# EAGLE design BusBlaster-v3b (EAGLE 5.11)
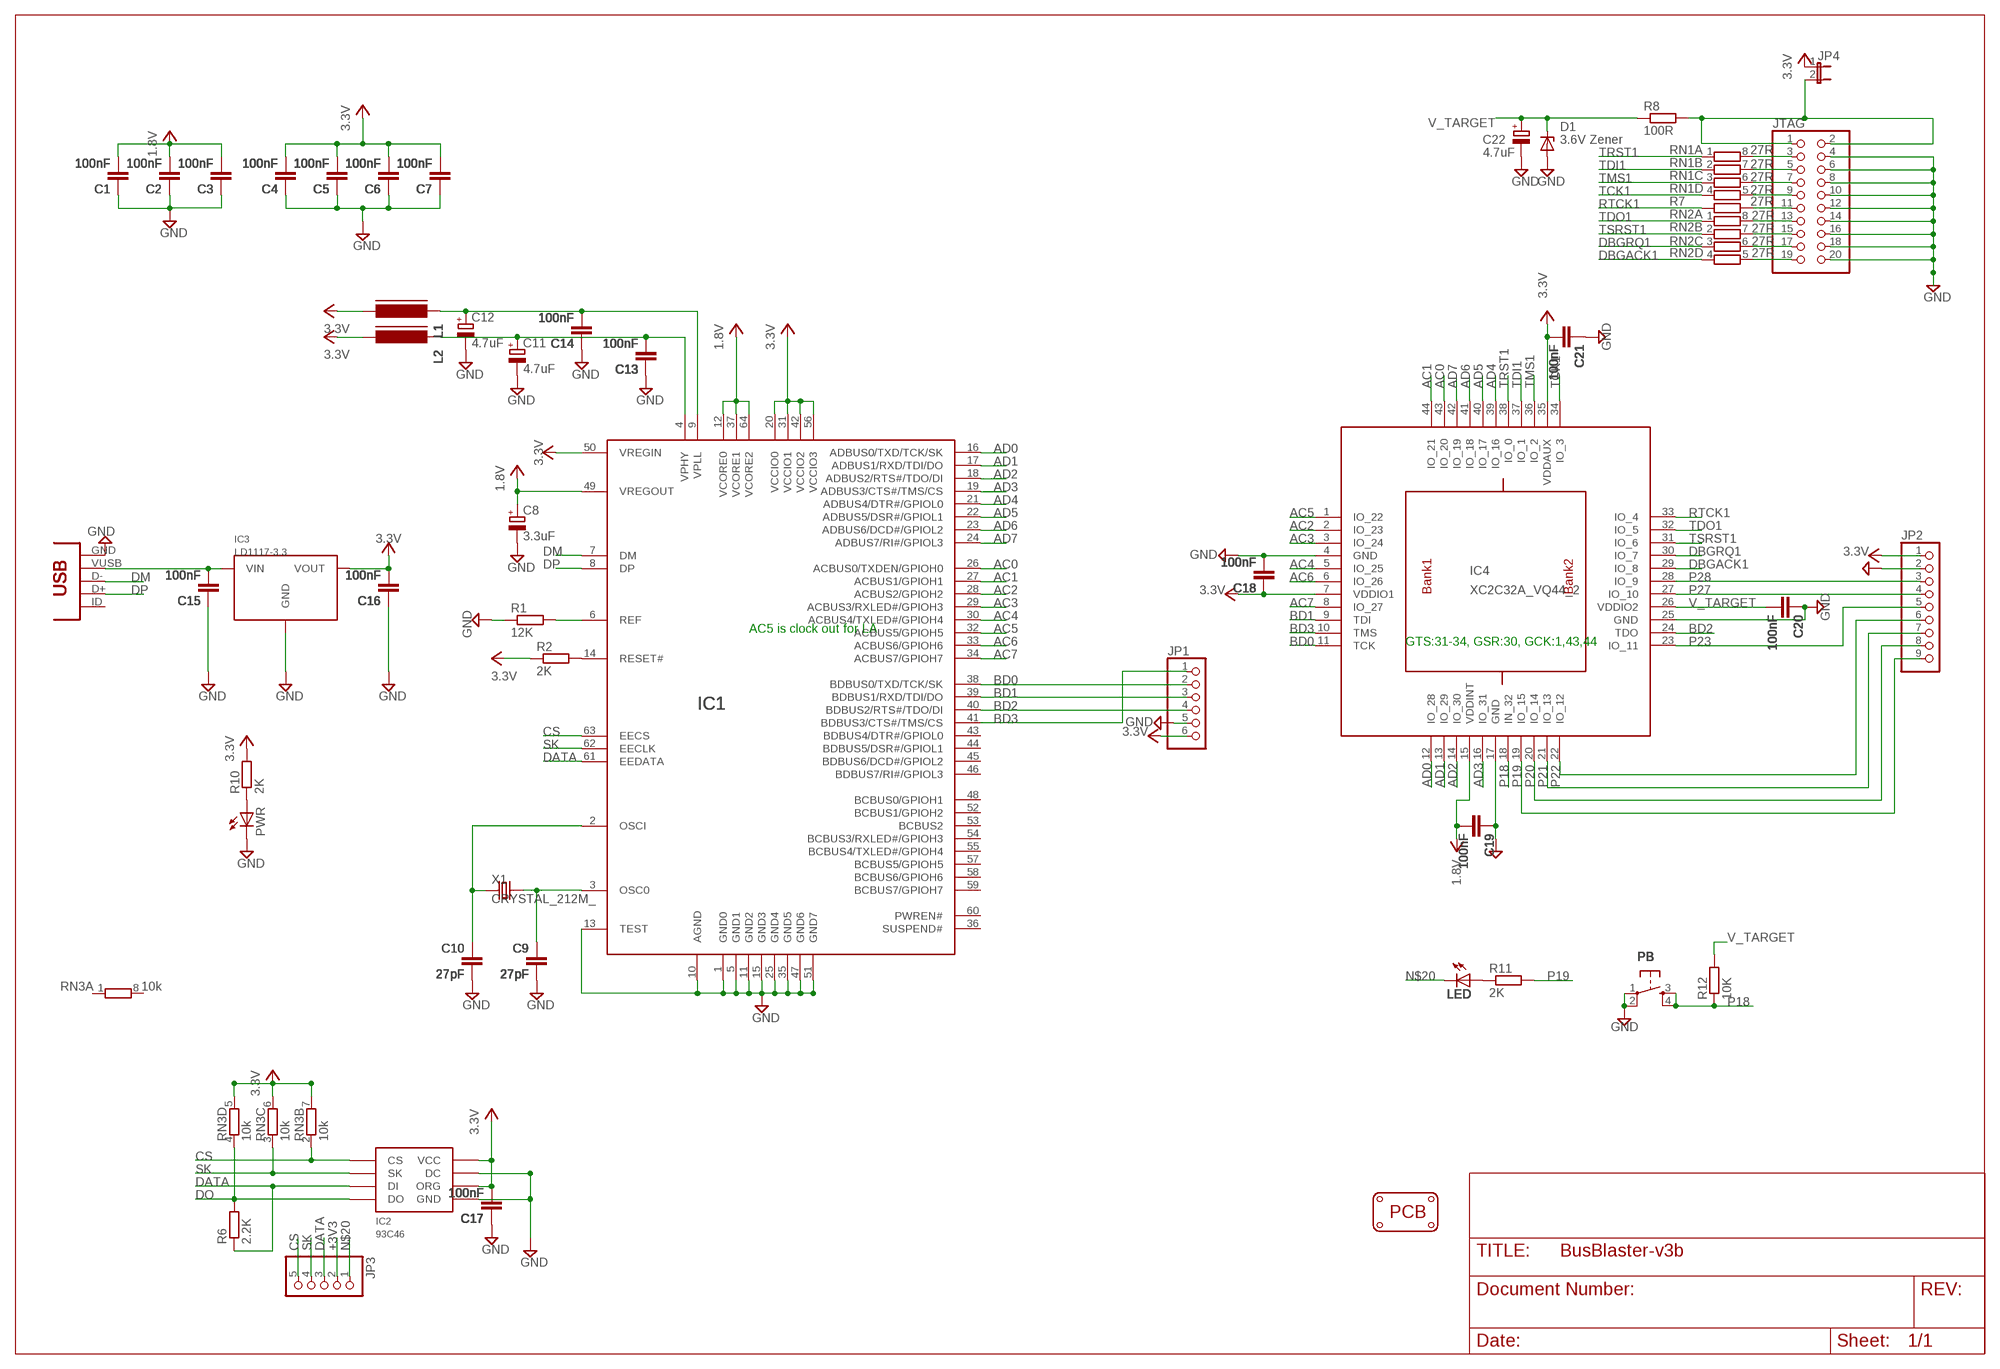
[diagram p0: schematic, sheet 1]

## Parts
C1  100nF  CAPC603  [C603]
C2  100nF  CAPC603  [C603]
C3  100nF  CAPC603  [C603]
C4  100nF  CAPC603  [C603]
C5  100nF  CAPC603  [C603]
C6  100nF  CAPC603  [C603]
C7  100nF  CAPC603  [C603]
C8  3.3uF  CAP_POLSMC_A  [SMC_A]
C9  27pF  CAPC603  [C603]
C10  27pF  CAPC603  [C603]
C11  4.7uF  CAP_POLSMC_A  [SMC_A]
C12  4.7uF  CAP_POLSMC_A  [SMC_A]
C13  100nF  CAPC603  [C603]
C14  100nF  CAPC603  [C603]
C15  100nF  CAPC603  [C603]
C16  100nF  CAPC603  [C603]
C17  100nF  CAPC603  [C603]
C18  100nF  CAPC603  [C603]
C19  100nF  CAPC603  [C603]
C20  100nF  CAPC603  [C603]
C21  100nF  CAPC603  [C603]
C22  4.7uF  CAP_POLSMC_A  [SMC_A]
D1  3.6V Zener  ZENERSOD-123  [SOD-123]
IC1  FT2232H  [LQFP64]
IC2  93C46  [SOIC8]
IC3  LD1117-3.3  [SOT223]
IC4  XC2C32A_VQ44_2  [VQ44]
JP1  PINHD-1X6  [1X06]
JP2  PINHD-1X9  [1X09]
JP3  PINHD-1X5  [1X05]
JP4  JP1EJP  [1X02]
JTAG  PINHEAD_-_COPY_PINHD-2X10SHROUDED  [PINHEAD_-_COPY_PINSHRD_PTH_2X10]
L1  FERRITE_BEAD603  [FB603]
L2  FERRITE_BEAD603  [FB603]
LED  LED805  [LED-805]
PB  SW-SMD-SMALL  [TACT_SWITCH_SMALL]
PCB3  PCB_DP_RECTANGLE-80X49  [DP8049_V1]
PWR  LEDCHIPLED_0805  [CHIPLED_0805]
R1  12K  RESISTORR603  [R603]
R2  2K  RESISTORR603  [R603]
R6  2.2K  RESISTORR603  [R603]
R7  27R  RESISTORR603  [R603]
R8  100R  RESISTORR1206  [R1206]
R10  2K  RESISTORR603  [R603]
R11  2K  RESISTORR603  [R603]
R12  10K  RESISTORR603  [R603]
RN1  27R  RNETWORK  [RN8P-4R-CRA06S]
RN2  27R  RNETWORK  [RN8P-4R-CRA06S]
RN3  10k  RNETWORK  [RN8P-4R-CRA06S]
USB  CON-USB-MINI-BUSB1  [CONN_USB_MINI-B]
X1  CRYSTAL_212M_  [4X6]

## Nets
1.8V: C1.2 C2.2 C3.2 C8.+ C19.2 IC1.12(VCORE0) IC1.37(VCORE1) IC1.49(VREGOUT) IC1.64(VCORE2) IC4.15(VDDINT)
+3V3: C4.2 C5.2 C6.2 C7.2 C16.2 C17.2 C18.1 C21.2 IC1.20(VCCIO0) IC1.31(VCCIO1) IC1.42(VCCIO2) IC1.50(VREGIN) IC1.56(VCCIO3) IC2.6(ORG) IC2.8(VCC) IC3.2(VOUT) IC4.7(VDDIO1) IC4.35(VDDAUX) JP1.6 JP2.1 JP3.2 JP4.1 L1.2 L2.2 R2.1 R10.2 RN3.5 RN3.6 RN3.7 ; supply symbol labelled 3.3V
AC0: IC1.26(ACBUS0/TXDEN/GPIOH0) IC4.43(IO_20)
AC1: IC1.27(ACBUS1/GPIOH1) IC4.44(IO_21)
AC2: IC1.28(ACBUS2/GPIOH2) IC4.2(IO_23)
AC3: IC1.29(ACBUS3/RXLED#/GPIOH3) IC4.3(IO_24)
AC4: IC1.30(ACBUS4/TXLED#/GPIOH4) IC4.5(IO_25)
AC5: IC1.32(ACBUS5/GPIOH5) IC4.1(IO_22)
AC6: IC1.33(ACBUS6/GPIOH6) IC4.6(IO_26)
AC7: IC1.34(ACBUS7/GPIOH7) IC4.8(IO_27)
AD0: IC1.16(ADBUS0/TXD/TCK/SK) IC4.12(IO_28)
AD1: IC1.17(ADBUS1/RXD/TDI/DO) IC4.13(IO_29)
AD2: IC1.18(ADBUS2/RTS#/TDO/DI) IC4.14(IO_30)
AD3: IC1.19(ADBUS3/CTS#/TMS/CS) IC4.16(IO_31)
AD4: IC1.21(ADBUS4/DTR#/GPIOL0) IC4.39(IO_16)
AD5: IC1.22(ADBUS5/DSR#/GPIOL1) IC4.40(IO_17)
AD6: IC1.23(ADBUS6/DCD#/GPIOL2) IC4.41(IO_18)
AD7: IC1.24(ADBUS7/RI#/GPIOL3) IC4.42(IO_19)
BD0: IC1.38(BDBUS0/TXD/TCK/SK) IC4.11(TCK) JP1.2
BD1: IC1.39(BDBUS1/RXD/TDI/DO) IC4.9(TDI) JP1.3
BD2: IC1.40(BDBUS2/RTS#/TDO/DI) IC4.24(TDO) JP1.4
BD3: IC1.41(BDBUS3/CTS#/TMS/CS) IC4.10(TMS) JP1.1
CS: IC1.63(EECS) IC2.1(CS) JP3.5 RN3.2
DATA: IC1.61(EEDATA) IC2.3(DI) JP3.3 R6.1
DBGACK1: IC4.29(IO_8) RN2.4
DBGRQ1: IC4.30(IO_7) RN2.3
DM: IC1.7(DM) USB.D-
DO: IC2.4(DO) R6.2 RN3.4
DP: IC1.8(DP) USB.D+
N$1: C9.1 IC1.3(OSC0) X1.2(X2)
N$2: C10.1 IC1.2(OSCI) X1.1(X1)
N$3: IC1.14(RESET#) R2.2
N$4: IC1.6(REF) R1.2
N$5: C15.2 IC3.3(VIN) USB.VUSB
N$6: PWR.A R10.1
N$7: JTAG.3 RN1.8
N$8: LED.A R11.1
N$9: JTAG.5 RN1.7
N$10: JTAG.7 RN1.6
N$11: JTAG.9 RN1.5
N$12: JTAG.11 R7.2
N$13: JTAG.13 RN2.8
N$14: JTAG.15 RN2.7
N$15: JTAG.17 RN2.6
N$16: JTAG.19 RN2.5
N$20: C1.1 C2.1 C3.1 C4.1 C5.1 C6.1 C7.1 C8.- C9.2 C10.2 C11.- C12.- C13.1 C14.1 C15.1 C16.1 C17.1 C18.2 C19.1 C20.1 C21.1 C22.- D1.A IC1.1(GND0) IC1.5(GND1) IC1.10(AGND) IC1.11(GND2) IC1.13(TEST) IC1.15(GND3) IC1.25(GND4) IC1.35(GND5) IC1.47(GND6) IC1.51(GND7) IC2.5(GND) IC2.7(DC) IC3.1(GND) IC4.4(GND) IC4.17(GND) IC4.25(GND) JP1.5 JP2.2 JP3.1 JTAG.4 JTAG.6 JTAG.8 JTAG.10 JTAG.12 JTAG.14 JTAG.16 JTAG.18 JTAG.20 LED.C PB.1 PB.2 PWR.C R1.1 USB.GND ; supply symbol labelled GND
P18: IC4.18(IN_32) PB.3 PB.4 R12.1
P19: IC4.19(IO_15) JP2.9 R11.2
P20: IC4.20(IO_14) JP2.8
P21: IC4.21(IO_13) JP2.7
P22: IC4.22(IO_12) JP2.6
P23: IC4.23(IO_11) JP2.5
P27: IC4.27(IO_10) JP2.4
P28: IC4.28(IO_9) JP2.3
RTCK1: IC4.33(IO_4) R7.1
SK: IC1.62(EECLK) IC2.2(SK) JP3.4 RN3.3
TCK1: IC4.34(IO_3) RN1.4
TDI1: IC4.37(IO_1) RN1.2
TDO1: IC4.32(IO_5) RN2.1
TMS1: IC4.36(IO_2) RN1.3
TRST1: IC4.38(IO_0) RN1.1
TSRST1: IC4.31(IO_6) RN2.2
V_TARGET: C20.2 C22.+ D1.C IC4.26(VDDIO2) R8.1 R12.2
V_TARGET_UNREG: JP4.2 JTAG.1 JTAG.2 R8.2
VPHY: C11.+ C13.2 IC1.4(VPHY) L2.1
VPLL: C12.+ C14.2 IC1.9(VPLL) L1.1
Unconnected: IC1.36(SUSPEND#) IC1.43(BDBUS4/DTR#/GPIOL0) IC1.44(BDBUS5/DSR#/GPIOL1) IC1.45(BDBUS6/DCD#/GPIOL2) IC1.46(BDBUS7/RI#/GPIOL3) IC1.48(BCBUS0/GPIOH1) IC1.52(BCBUS1/GPIOH2) IC1.53(BCBUS2) IC1.54(BCBUS3/RXLED#/GPIOH3) IC1.55(BCBUS4/TXLED#/GPIOH4) IC1.57(BCBUS5/GPIOH5) IC1.58(BCBUS6/GPIOH6) IC1.59(BCBUS7/GPIOH7) IC1.60(PWREN#) RN3.1 RN3.8 USB.BODY@1(BODY) USB.BODY@2(BODY) USB.BODY@3(BODY) USB.BODY@4(BODY) USB.ID(USBID)

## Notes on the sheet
- AC5 is clock out for LA
- GTS:31-34, GSR:30, GCK:1,43,44

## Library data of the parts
C1-C7 C9 C10 C13-C21 = dp_devices:CAP
C8 C11 C12 C22 = DP-EagleLibrary:CAP_POL
D1 = dp_devices:ZENER: Zener Diode SOD-323
IC1 = dp_devices:FT2232H: DUAL HIGH SPEED USB TO MULTIPURPOSE UART/FIFO IC
IC2 = DP-EagleLibrary:93C46
IC3 = DP-EagleLibrary:LD1117-3.3
IC4 = dp_devices:XC2C32A_VQ44_2: xc2c32a_vq44-ian edit this description Auto generated by make-symbol-device-package-bsdl.ulp Rev. 29 Source: xc2c32a_vq44-ian.bsd
JP1 = pinhead:PINHD-1X6: PIN HEADER
JP2 = pinhead - Copy:PINHD-1X9: PIN HEADER
JP3 = pinhead:PINHD-1X5: PIN HEADER
JP4 = jumper:JP1E: JUMPER
JTAG = LPC1768board:PINHEAD_-_COPY_PINHD-2X10: PIN HEADER
L1 L2 = dp_devices:FERRITE_BEAD
LED = dp_devices:LED
PB = dp_devices:SW-SMD-SMALL
PCB3 = dp_devices:PCB_DP_RECTANGLE: Dangerous Prototypes Standard Rectangular PCB sizes
PWR = led:LED: LED
R1 R2 R6-R8 R10-R12 = dp_devices:RESISTOR
RN1-RN3 = dp_devices:RNETWORK: 4 Resistor Array 0603
USB = dp_devices:CON-USB-MINI-B: USB connector
X1 = dp_devices:CRYSTAL_2

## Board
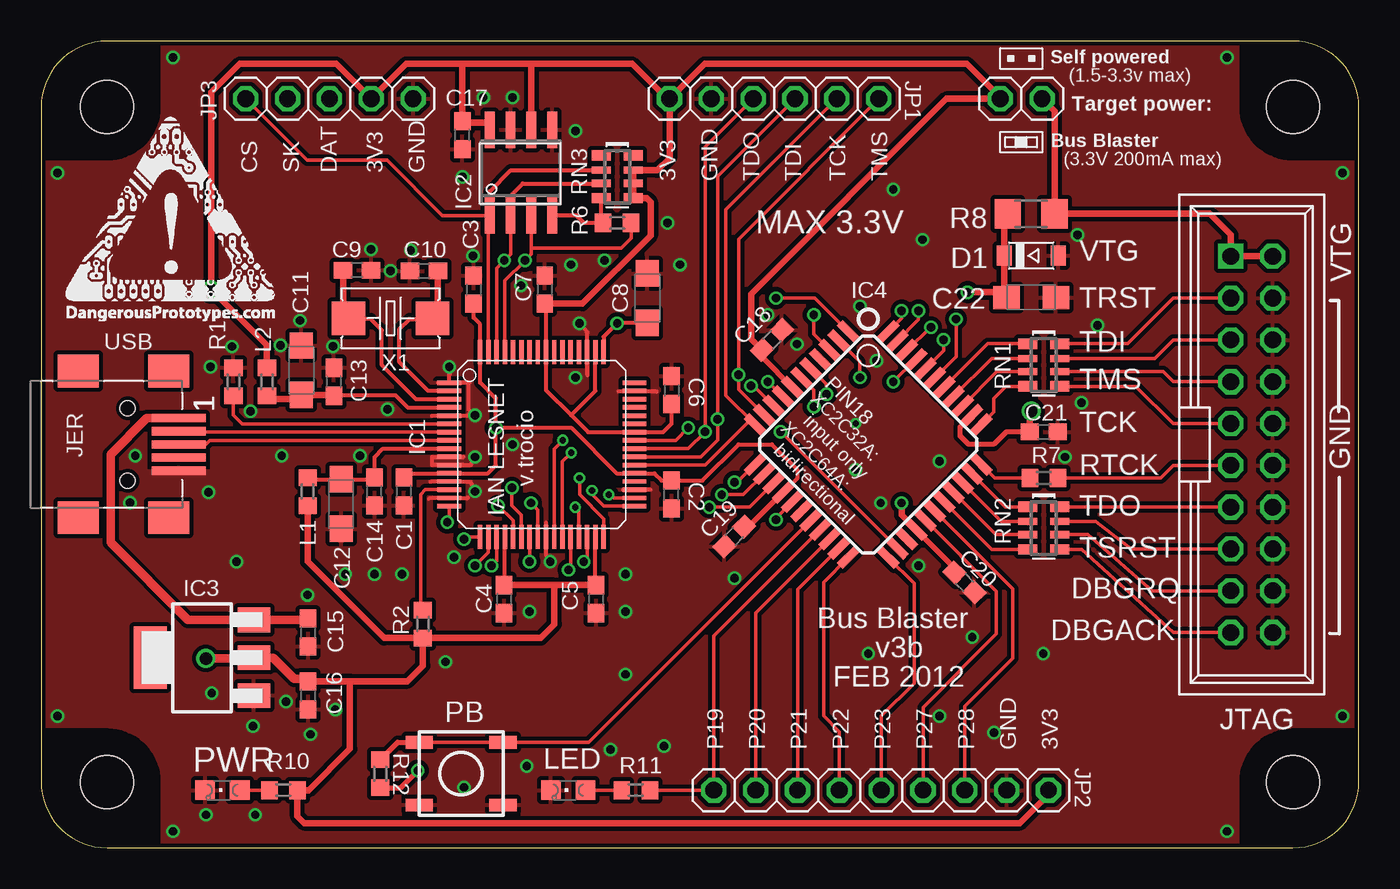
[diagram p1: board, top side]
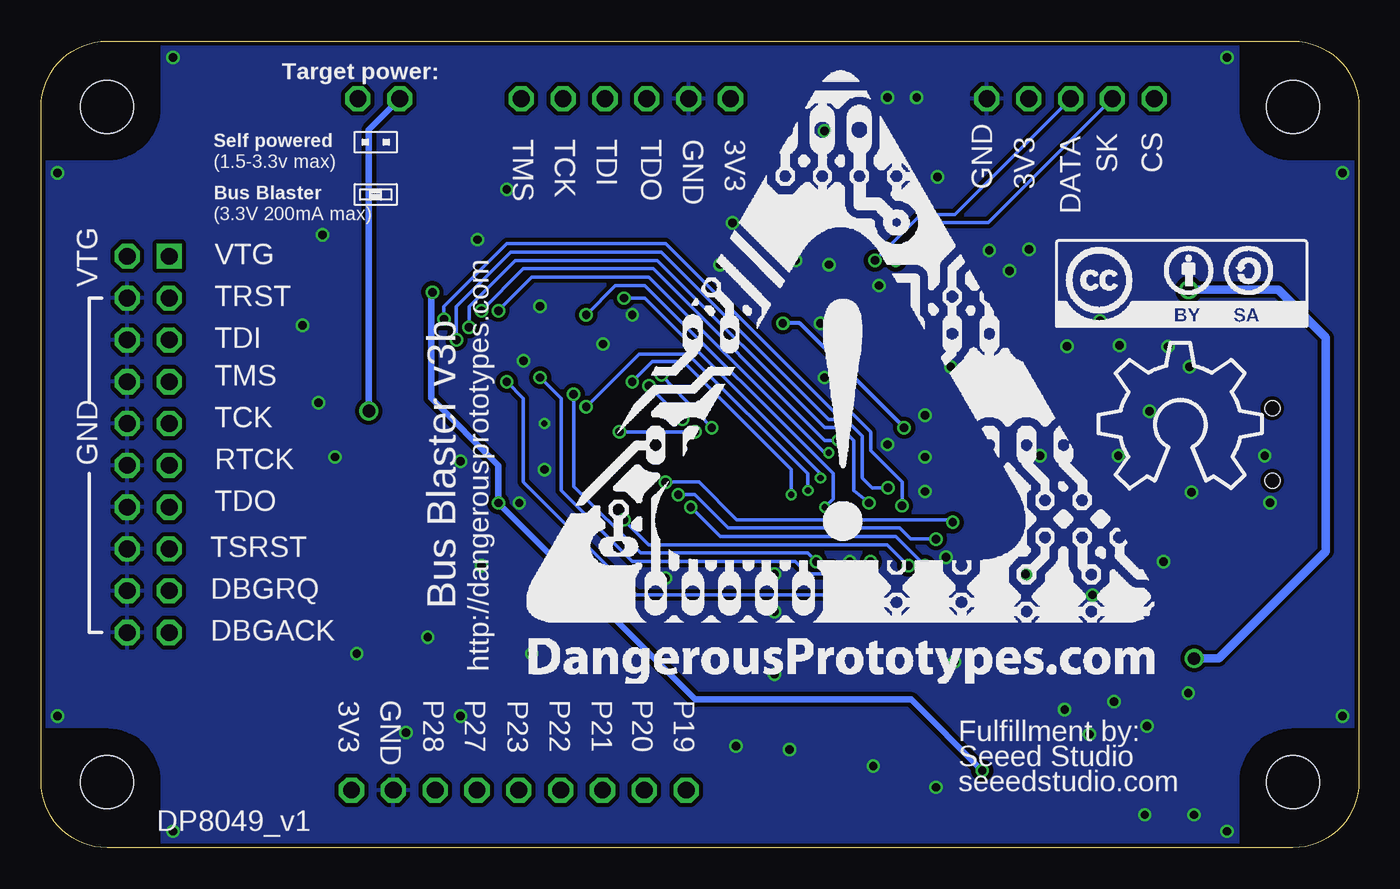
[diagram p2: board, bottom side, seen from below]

Size 80 x 49 mm. Coordinates in mm from the lower left corner, seen from the top.
Copper layers (1*16): Top 0.035mm / dielectric 1.5mm / Bottom 0.035mm
Design rules "Fusion_eagle_rule_v1.1": minimum track width 6mil, minimum drill 12mil, track to track 6mil, track to pad 6mil, pad to pad 6mil, via to via 6mil, smd to smd 0mil, copper to edge 10mil, drill to drill 10mil, minimum pad ring 10mil, minimum via ring 6mil, stop-mask expansion 2mil, vias tented up to drill 100mil, thermal gap 10mil

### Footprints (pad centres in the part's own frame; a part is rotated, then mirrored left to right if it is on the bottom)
C603 = smd 1.1 x 1: 1 -0.85,0; 2 0.85,0
SMC_A = smd 1.6 x 1.4: + -1.5,0; - 1.5,0
SOD-123 = smd 0.91 x 1.22: A 1.635,0; C -1.635,0
LQFP64 = smd 1.45 x 0.27: 1 -5.625,3.75; 2 -5.625,3.25; 3 -5.625,2.75; 4 -5.625,2.25; 5 -5.625,1.75; 6 -5.625,1.25; 7 -5.625,0.75; 8 -5.625,0.25; 9 -5.625,-0.25; 10 -5.625,-0.75; 11 -5.625,-1.25; 12 -5.625,-1.75; 13 -5.625,-2.25; 14 -5.625,-2.75; 15 -5.625,-3.25; 16 -5.625,-3.75; 33 5.625,-3.75; 34 5.625,-3.25; 35 5.625,-2.75; 36 5.625,-2.25; 37 5.625,-1.75; 38 5.625,-1.25; 39 5.625,-0.75; 40 5.625,-0.25; 41 5.625,0.25; 42 5.625,0.75; 43 5.625,1.25; 44 5.625,1.75; 45 5.625,2.25; 46 5.625,2.75; 47 5.625,3.25; 48 5.625,3.75 | smd 0.27 x 1.45: 17 -3.75,-5.625; 18 -3.25,-5.625; 19 -2.75,-5.625; 20 -2.25,-5.625; 21 -1.75,-5.625; 22 -1.25,-5.625; 23 -0.75,-5.625; 24 -0.25,-5.625; 25 0.25,-5.625; 26 0.75,-5.625; 27 1.25,-5.625; 28 1.75,-5.625; 29 2.25,-5.625; 30 2.75,-5.625; 31 3.25,-5.625; 32 3.75,-5.625; 49 3.75,5.625; 50 3.25,5.625; 51 2.75,5.625; 52 2.25,5.625; 53 1.75,5.625; 54 1.25,5.625; 55 0.75,5.625; 56 0.25,5.625; 57 -0.25,5.625; 58 -0.75,5.625; 59 -1.25,5.625; 60 -1.75,5.625; 61 -2.25,5.625; 62 -2.75,5.625; 63 -3.25,5.625; 64 -3.75,5.625
SOIC8 = smd 0.6 x 2.2: 1 -1.905,-2.6; 2 -0.635,-2.6; 3 0.635,-2.6; 4 1.905,-2.6; 5 1.905,2.6; 6 0.635,2.6; 7 -0.635,2.6; 8 -1.905,2.6
SOT223 = smd 1.5 x 2: 1 -2.3,-3.15; 2 0,-3.15; 3 2.3,-3.15 | smd 3.8 x 2: 4 0,3.15
VQ44 = smd 1.5 x 0.5: 1 -5.7,4; 2 -5.7,3.2; 3 -5.7,2.4; 4 -5.7,1.6; 5 -5.7,0.8; 6 -5.7,0; 7 -5.7,-0.8; 8 -5.7,-1.6; 9 -5.7,-2.4; 10 -5.7,-3.2; 11 -5.7,-4; 23 5.7,-4; 24 5.7,-3.2; 25 5.7,-2.4; 26 5.7,-1.6; 27 5.7,-0.8; 28 5.7,0; 29 5.7,0.8; 30 5.7,1.6; 31 5.7,2.4; 32 5.7,3.2; 33 5.7,4 | smd 0.5 x 1.5: 12 -4,-5.7; 13 -3.2,-5.7; 14 -2.4,-5.7; 15 -1.6,-5.7; 16 -0.8,-5.7; 17 0,-5.7; 18 0.8,-5.7; 19 1.6,-5.7; 20 2.4,-5.7; 21 3.2,-5.7; 22 4,-5.7; 34 4,5.7; 35 3.2,5.7; 36 2.4,5.7; 37 1.6,5.7; 38 0.8,5.7; 39 0,5.7; 40 -0.8,5.7; 41 -1.6,5.7; 42 -2.4,5.7; 43 -3.2,5.7; 44 -4,5.7
1X06 = drill 1.016 octagon: 1 -6.35,0; 2 -3.81,0; 3 -1.27,0; 4 1.27,0; 5 3.81,0; 6 6.35,0
1X09 = drill 1.016 octagon: 1 -10.16,0; 2 -7.62,0; 3 -5.08,0; 4 -2.54,0; 5 0,0; 6 2.54,0; 7 5.08,0; 8 7.62,0; 9 10.16,0
1X05 = drill 1.016 octagon: 1 -5.08,0; 2 -2.54,0; 3 0,0; 4 2.54,0; 5 5.08,0
1X02 = drill 1.016 octagon: 1 -1.27,0; 2 1.27,0
PINHEAD_-_COPY_PINSHRD_PTH_2X10 = drill 1.016 square: 1 -11.43,-1.27 | drill 1.016 octagon: 2 -11.43,1.27; 3 -8.89,-1.27; 4 -8.89,1.27; 5 -6.35,-1.27; 6 -6.35,1.27; 7 -3.81,-1.27; 8 -3.81,1.27; 9 -1.27,-1.27; 10 -1.27,1.27; 11 1.27,-1.27; 12 1.27,1.27; 13 3.81,-1.27; 14 3.81,1.27; 15 6.35,-1.27; 16 6.35,1.27; 17 8.89,-1.27; 18 8.89,1.27; 19 11.43,-1.27; 20 11.43,1.27
FB603 = smd 1 x 1.1: 1 -0.85,0; 2 0.85,0
LED-805 = smd 1.2 x 1.2: A 0,-1.05; C 0,1.05
TACT_SWITCH_SMALL = smd 1.651 x 0.762: 1 -2.54,1.905; 2 2.54,1.905; 3 -2.54,-1.905; 4 2.54,-1.905
DP8049_V1 = hole 3.2: 4,4; 76,4; 76,45; 4,45
CHIPLED_0805 = smd 1.2 x 1.2: A 0,-1.05; C 0,1.05
R603 = smd 1 x 1.1: 1 -0.85,0; 2 0.85,0
R1206 = smd 1.6 x 1.803: 1 -1.422,0; 2 1.422,0
RN8P-4R-CRA06S = smd 0.63 x 1.15: 1 -1.295,-0.975; 4 1.295,-0.975; 5 1.295,0.975; 8 -1.295,0.975 | smd 0.44 x 1.15: 2 -0.4,-0.975; 3 0.4,-0.975; 6 0.4,0.975; 7 -0.4,0.975
CONN_USB_MINI-B = smd 2 x 2.5: BODY@1 -4.45,2.5; BODY@2 4.45,2.5; BODY@3 4.45,-3; BODY@4 -4.45,-3 | smd 0.5 x 3.3: D+ 0,3.1; D- -0.8,3.1; GND 1.6,3.1; ID 0.8,3.1; VUSB -1.6,3.1 | hole 0.9: -2.2,0; 2.2,0
4X6@1 = smd 2.032 x 2.032: 1 -2.54,0; 2 2.54,0

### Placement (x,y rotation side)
C1  22.02,21.64 90 top
C2  38.27,21.46 90 top
C3  26.26,33.9 270 top
C4  28.11,15.1 90 top
C5  33.7,15.1 90 top
C6  38.27,27.8 270 top
C7  30.57,33.9 270 top
C8  36.8,33.39 90 top
C9  19.18,35.09 0 top
C10  23.24,35.04 180 top
C11  15.8,29.01 90 top
C12  18.21,20.88 270 top
C13  17.77,28.31 270 top
C14  20.24,21.64 90 top
C15  16.21,13.07 90 top
C16  16.21,9.26 90 top
C17  25.57,43.3 90 top
C18  44.37,30.85 45 top
C19  42.08,18.91 45 top
C20  56.05,16.12 135 top
C21  60.87,25.26 180 top
C22  60.11,33.43 0 top
D1  60.11,35.97 0 top
IC1  30.4,24.5 0 top
IC2  29.13,41.01 0 top
IC3  9.77,11.55 90 top
IC4  50.21,24.5 315 top
JP1  44.5,45.5 180 top
JP2  51,3.5 180 top
JP3  17.5,45.5 180 top
JP4  59.5,45.5 0 top
JTAG  73.5,24.5 270 top
L1  16.18,21.64 270 top
L2  13.71,28.31 90 top
LED  32,3.5 90 top
PB  25.5,4.5 180 top
PCB3  0,0 0 top
PWR  11,3.5 90 top
R1  11.68,28.31 270 top
R2  23.18,13.6 90 top
R6  34.97,37.96 180 top
R7  60.87,22.47 0 top
R8  60.11,38.51 0 top
R10  14.7,3.5 0 top
R11  36.1,3.5 0 top
R12  20.59,4.5 270 top
RN1  60.87,29.33 270 top
RN2  60.87,19.42 270 top
RN3  34.97,40.76 270 top
U$1  [DP_LOGO_ART_1.5X1.5]  50.5,10 0 bottom
U$2  [DP_LOGO_ART_0.5X0.5]  1.5,32 0 top
U$3  [CC-BY-SA]  18.42,31.63 0 bottom
U$5  [OSHW_10X350_NOTEXT]  15.8,21.82 0 bottom
U$6  adasdsd  [JUMP2_DESC_ON]  59.69,39.69 0 bottom
U$7  [JUMP2_DESC_OFF]  59.69,42.86 0 bottom
U$8  [JUMP2_DESC_OFF]  59.5,47.94 0 top
U$9  adasdsd  [JUMP2_DESC_ON]  59.5,42.86 0 top
USB  5.25,24.5 270 top
X1  CRYSTAL_212M_  [4X6@1]  21.21,32.17 180 top

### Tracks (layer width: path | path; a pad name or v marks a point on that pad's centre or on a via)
1.8V  (via drill 0.51)
  Top 0.254: C1.2 22.08,22.43 21.91,22.54 22.11,22.75 IC1.12 27.13,22.75 27.61,23.23 v27.61,25.52 | C3.2 26.26,32.2 26.65,31.81 IC1.64 26.65,28.25 27.61,27.29 v27.61,25.52 | v27.61,25.52 32.18,25.52 34.94,22.75 IC1.37 37.23,22.75 37.67,22.31 C2.2 40.14,22.31 42.34,24.5 44.37,24.5 45.89,22.98 45.89,22.45 IC4.15 | C8.+ 35,31.89 v34.97,31.87 34.15,31.04 IC1.49
  Top 0.305: IC4.15 42.96,19.51 C19.2
  Bottom 0.254: v34.97,31.87 33.96,31.87 v27.61,25.52
+3V3  (via drill 0.76)
  Top 0.254: IC1.20 28.15,15.99 C4.2 | C7.2 30.65,32.97 IC1.56 30.65,27.81 32.18,26.28 | IC1.31 33.65,16 C5.2 | C6.2 38.27,25.76 37.77,25.25 IC1.42 33.21,25.25 32.18,26.28 | IC1.50 33.65,27.75 32.18,26.28
  Top 0.305: 43.77,30.43 C18.1 43.77,29.81 IC4.7 | C21.2 58.59,25.26 57.83,24.5 56.31,24.5 55.8,25.01 55.8,25.56 IC4.35
  Top 0.406: IC2.8 27.23,43.93 27.1,44.06 25.66,44.06 C17.2 25.57,47.62 | C7.2 32.85,33.05 37,37.2 37,39.23 36.77,39.46 RN3.5 RN3.6 RN3.7 37.4,41.16 38.15,41.9 JP1.6 | L1.2 16.18,17.39 20.82,12.75 R2.1 | 31.16,15.95 C4.2 | 31.16,15.95 C5.2 | C18.1 43.1,30.92 43.1,33.64 54.96,45.5 JP4.1 58.23,45.59 56.2,47.62 40.27,47.62 JP1.6 | 31.16,15.95 31.16,13.58 30.33,12.75 R2.1 | v60.11,26.53 60.02,26.44 C21.2 | 16.12,10.12 16.14,10.11 18.75,10.11 | 18.75,10.11 18.75,6 16.24,3.49 R10.2 | 18.75,10.11 22.24,10.11 23.18,11.05 R2.1 | L2.2 13.71,30.52 v10.33,33.9 10.33,45.89 12.06,47.62 17.91,47.62 JP3.2 22.16,47.62 25.57,47.62 | JP1.6 38,45.5 35.88,47.62 29.77,47.62 | 25.57,47.62 29.77,47.62 | 29.77,47.62 IC2.6 | JP2.1 61.16,3.24 59.42,1.5 15.96,1.5 15.56,1.91 R10.2 | R10.2
  Top 0.508: 16.07,10.25 15.38,10.25 14.08,11.55 IC3.2 12.87,11.5 v10,11.5 | 16.07,10.25 C16.2 | 16.07,10.25 16.07,10.18 16.12,10.12
  Bottom 0.406: v60.11,26.53 60.11,43.62 JP4.1
  Bottom 0.508: v10.33,33.9 4.9,33.9 2,31 2,18 8.5,11.5 v10,11.5
AC0  (via drill 0.38, 0.51)
  Top 0.203: IC1.26 31.15,24.23 v31.67,24.75 | v53.26,32.63 53.26,32.07 IC4.43
  Bottom 0.203: v31.67,24.75 32.43,24.75 42.85,35.17 50.72,35.17 v53.26,32.63
AC1  (via drill 0.38, 0.51)
  Top 0.203: IC1.27 31.65,23.46 v32.18,23.99 | v52.24,32.63 52.24,32.19 IC4.44
  Bottom 0.203: v32.18,23.99 32.43,23.99 43.1,34.66 50.21,34.66 v52.24,32.63
AC2  (via drill 0.51)
  Top 0.203: v49.7,28.56 49.7,29.53 IC4.2 | IC1.28 32.15,17.01 v32.02,16.88
  Bottom 0.203: v49.7,28.56 48.43,27.29 48.43,21.71 44.12,17.39 34.21,17.39 33.45,16.63 32.27,16.63 v32.02,16.88
AC3  (via drill 0.38, 0.51)
  Top 0.203: IC1.29 32.65,20.47 v32.43,20.69 | v46.91,32.37 46.91,31.2 IC4.3
  Bottom 0.203: v32.43,20.69 31.92,21.2 31.92,22.72 43.35,34.15 45.13,34.15 v46.91,32.37
AC4  (via drill 0.51)
  Top 0.203: IC1.30 33.15,17.6 v32.94,17.39 | v47.67,27.55 47.67,28.17 IC4.5
  Bottom 0.203: v32.94,17.39 33.45,17.9 43.61,17.9 47.67,21.96 v47.67,27.55
AC5  (via drill 0.38, 0.51)
  Top 0.203: IC1.32 34.15,19.99 32.69,21.45 v32.69,22.47 | IC4.1 46.98,33.39 v44.62,33.39
  Bottom 0.203: v32.69,22.47 32.69,22.72 43.35,33.39 v44.62,33.39
AC6  (via drill 0.38, 0.51)
  Top 0.203: IC1.33 34.15,20.75 33.45,21.45 v33.45,21.71 | v46.91,26.79 46.91,27.8 IC4.6
  Bottom 0.203: v33.45,21.71 33.45,22.72 40.73,30 43.69,30 v46.91,26.79
AC7  (via drill 0.38, 0.51)
  Top 0.203: IC1.34 34.77,21.25 v34.46,21.45 | v44.12,28.31 45.03,27.4 IC4.8
  Bottom 0.203: v34.46,21.45 34.46,22.98 41.02,29.53 42.9,29.53 v44.12,28.31
AD0  (via drill 0.51)
  Top 0.203: v42.08,22.21 42.27,22.21 IC4.12 | IC1.16 24.77,19.89 v24.65,19.77
  Bottom 0.203: v42.08,22.21 40.05,22.21 37.77,19.93 24.81,19.93 v24.65,19.77
AD1  (via drill 0.51)
  Top 0.203: v41.32,21.45 42.64,21.45 IC4.13 | IC1.17 25.86,18.88 v25.67,18.75
  Bottom 0.203: v41.32,21.45 40.31,21.45 38.27,19.42 27.86,19.42 27.19,18.75 v25.67,18.75
AD2  (via drill 0.51)
  Top 0.203: v40.56,20.69 43.01,20.69 IC4.14 | IC1.18 27.15,17.95 v26.34,17.13
  Bottom 0.203: v26.34,17.13 28.11,18.91 38.78,18.91 v40.56,20.69
AD3  (via drill 0.51)
  Top 0.203: IC1.19 27.65,17.43 v27.35,17.13 | v44.62,19.93 44.51,19.93 IC4.16
  Bottom 0.203: v27.35,17.13 28.62,18.4 43.1,18.4 v44.62,19.93
AD4  (via drill 0.51)
  Top 0.203: v55.55,32.12 55.55,29.83 IC4.39 | IC1.21 28.65,19.87 v27.73,20.79
  Bottom 0.203: v55.55,32.12 55.55,32.88 51.74,36.69 42.08,36.69 31.92,26.53 30.91,26.53 29.64,25.26 29.64,24.13 27.73,22.23 v27.73,20.79
AD5  (via drill 0.51)
  Top 0.203: v54.78,30.85 54.78,30.2 IC4.40 | IC1.22 29.15,20.22 28.57,20.8 28.57,21.85 v28.59,21.86
  Bottom 0.203: v54.78,30.85 54.78,32.88 51.48,36.18 42.34,36.18 32.18,26.02 31.16,26.02 30.15,25.01 30.15,22.47 29.54,21.86 v28.59,21.86
AD6  (via drill 0.51)
  Top 0.203: IC1.23 v29.65,17.4 v29.64,17.39 | v51.74,28.31 53.09,29.66 IC4.41
  Bottom 0.203: v29.64,17.39 31.67,15.36 43.86,15.36 50.72,22.21 50.72,27.29 v51.74,28.31
AD7  (via drill 0.51)
  Top 0.203: 54.02,31.7 v54.02,31.61 IC4.42 | IC1.24 30.15,20.53 v29.73,20.94
  Bottom 0.203: v54.02,31.61 54.02,32.88 51.23,35.68 42.59,35.68 32.43,25.52 31.42,25.52 30.65,24.75 30.65,21.71 v29.73,20.94
BD0
  Top 0.203: IC1.38 40.33,23.25 42.97,25.9 | 42.97,25.9 43.1,26.02 | 42.97,25.9 43.17,25.7 IC4.11 41.58,27.48 41.58,38.77 JP1.2
BD1  (via drill 0.51)
  Top 0.203: IC1.39 40.05,23.75 41.07,24.77 v41.07,26.02 41.07,40.8 JP1.3 | IC4.9 43.26,28.06 v43.1,28.06
  Bottom 0.203: v41.07,26.02 v43.1,28.06
BD2  (via drill 0.51)
  Top 0.203: IC1.40 39.29,24.25 v40.31,25.27 | IC4.24 44.92,25.26 v44.88,25.26 | v40.31,25.27 v40.31,25.26 | v40.31,25.27 40.31,42.58 JP1.4
  Bottom 0.203: v40.31,25.26 v44.88,25.26
BD3  (via drill 0.51)
  Top 0.203: IC1.41 38.52,24.75 v39.29,25.52 | IC4.10 42.34,27.85 v42.34,28.72 42.34,36.99 JP1.1
  Bottom 0.203: 39.24,25.52 v39.29,25.52 v42.34,28.72
CS
  Top 0.203: IC1.63 27.15,38.34 IC2.1 24.36,38.41 21,41.77 16.15,41.77 JP3.5
  Top 0.254: RN3.2 28.51,41.16 27.23,39.87 IC2.1
DATA  (via drill 0.51)
  Top 0.203: IC1.61 28.15,34.44 v29.38,35.68 29.77,36.06 29.77,36.44 | 29.77,36.44 IC2.3 | R6.1 35.82,37.03 35.23,36.44 29.77,36.44
  Bottom 0.203: v29.38,35.68 26.59,38.47 24.53,38.47 JP3.3
DBGACK1
  Top 0.203: IC4.29 57.72,18.12 RN2.4
DBGRQ1
  Top 0.203: IC4.30 57.95,19.02 RN2.3
DM
  Top 0.203: IC1.7 8.23,25.25 USB.D-
DO
  Top 0.254: RN3.4 34,38.09 R6.2 32.94,37.96 32.49,38.41 IC2.4
DP
  Top 0.203: IC1.8 10.23,24.75 9.98,24.5 USB.D+
N$1
  Top 0.254: IC1.3 22.75,27.25 20.69,29.31 20.69,31.44 20,32.12 19.21,32.12 X1.2
  Top 0.406: C9.1 18.33,32.51 X1.2
N$2
  Top 0.254: IC1.2 23.5,27.75 21.75,29.5 21.75,31.5 22.38,32.12 24.2,32.12 X1.1
  Top 0.406: C10.1 24.09,32.51 X1.1
N$3
  Top 0.203: IC1.14 23.33,21.75 23.03,21.45 23.03,14.59 R2.2
N$4
  Top 0.203: IC1.6 12.2,25.75 11.68,26.28 R1.2
N$5
  Top 0.508: USB.VUSB 6.42,26.1 4.21,23.89 4.21,18.54 8.9,13.85 IC3.3 16.13,13.85 C15.2
N$6
  Top 0.203: PWR.A R10.1
N$7
  Top 0.203: RN1.8 65.96,30.62 68.73,33.39 JTAG.3
N$8
  Top 0.203: LED.A R11.1
N$9
  Top 0.203: RN1.7 67.61,29.73 68.73,30.85 JTAG.5
N$10
  Top 0.203: RN1.6 68.11,28.93 68.73,28.31 JTAG.7
N$11
  Top 0.203: RN1.5 66.47,28.03 68.73,25.77 JTAG.9
N$12
  Top 0.203: R7.2 67.97,22.47 68.73,23.23 JTAG.11
N$13
  Top 0.203: RN2.8 61.87,20.69 JTAG.13
N$14
  Top 0.203: RN2.7 64.02,19.82 66.19,18.15 JTAG.15
N$15
  Top 0.203: JTAG.17 67.46,15.61 63.55,19.02 RN2.6
N$16
  Top 0.203: RN2.5 63.17,18.12 68.73,13.07 JTAG.19
N$20  (via drill 0.38, 0.51)
  Top 0.203: 30.65,17.84 30.66,17.84 | 23.8,21.25 23.6,21.25 23.54,21.2 | 30.7,17.75 30.7,17.43 v30.91,17.39
  Top 0.254: 30.65,19.42 30.65,17.84 30.65,17.8 30.7,17.75 | 30.65,19.42 30.65,19.76 | IC1.15 23.8,21.25 | 25.32,22.24 23.65,22.24 | 25.66,23.24 23.74,23.24 23.73,23.25 23.73,23.75 25.65,23.75 | 23.72,26.24 25.64,26.24 25.63,26.25 | 35.05,27.74 36.03,27.74 | 35.32,21.75 36.98,21.75 | 24.1,28.25 26.02,28.25 | IC1.5 25.63,26.25 | 24.81,28.79 24.77,28.75 IC1.1 25.95,28.25 25.96,28.25 25.96,26.63 26.12,26.47 25.9,26.25 25.63,26.25 | IC1.51 33.15,29.22 33.16,28.71 33.16,31.32 v32.69,31.87 | 36.03,27.74 IC1.47 | 36.03,27.74 37.33,27.74 37.37,27.7 | IC1.11 25.64,23.25 25.66,23.24 | IC1.13 25.31,22.25 25.32,22.24 | IC1.15 | 25.66,23.24 25.9,23.24 | 25.9,23.24 25.91,23.23 | IC1.15 25.89,21.25 25.9,21.27 | IC1.25 30.65,19.42 | 36.98,21.75 IC1.35 | 36.98,21.75 | 25.32,22.24 26.05,22.24 v26.34,21.64 | 25.9,23.24 26.09,23.24 v26.34,23.74
  other vias: 79,8 26.84,45.58 28.62,45.58 32.43,28.56 32.18,35.42 29.13,34.15 26.34,26.28 28.62,24.5 21.21,35.05 20.03,36.36 26.21,35.95 19.37,23.81 14.61,23.81 10.16,21.59 5.71,23.81 5.4,20.95 21.91,16.63 18.46,16.63 11.86,17.39 16.18,15.36 20.25,16.63 10,2 13,2 37.8,6.17 25.67,3.67 29.48,4.96 34.57,5.96 53.26,17.13 60.84,11.8 57.84,6.99 63.16,27.04 62.16,23.74 50.21,11.8 56.53,12.8 54.53,7.99 45.89,30.6 51.74,39.99 53.51,36.95 38.02,37.96 32.43,43.55 25.57,40.76 44.12,32.37 35.48,14.34 35.48,16.63 42.08,16.37 35.48,10.53 24.56,11.29 29.64,14.34 25.07,17.64 38.78,35.42 34.21,35.68 62.92,37.22 64.14,31.74 50.72,29.58 49.45,22.98 49.45,25.77 54.53,23.48 50.97,20.94 49.7,32.88 22.44,36.29 12.86,7.39 10.36,9.39 14.86,8.89 16.36,6.89 17.86,8.39 24.77,29.22 17.71,30.47 14.52,30.53 15.71,32.03 10.27,29.22 11.59,30.45 21.03,26.64 12.71,26.51 79,41 72,48 1,41 8,48 1,8 8,1 72,1
  pour Bottom (isolate 0.254): 0,0 80,0 80,49 0,49
  pour Top (isolate 0.254): 0,0 80,0 80,49 0,49
  pour Top (no thermals): 6.35,22.86 10.48,22.86 10.48,22.54 10.16,22.23 6.67,22.23 6.35,22.54
  pour Top (no thermals): 23.81,23.81 26.04,23.81 26.04,23.18 23.81,23.18
P18
  Top 0.203: PB.4 PB.3 33.25,6.41 IC4.18
  Top 0.305: PB.4 21.64,6.41 R12.1
P19
  Top 0.203: R11.2 JP2.9 40.84,12.87 IC4.19
P20
  Top 0.203: JP2.8 43.38,14.27 IC4.20
P21
  Top 0.203: JP2.7 45.92,15.68 IC4.21
P22
  Top 0.203: IC4.22 47.5,16.13 47.5,8 48.46,7.04 JP2.6
P23
  Top 0.203: IC4.23 53,16.05 53,10 51,8 JP2.5
P27
  Top 0.203: IC4.27 58,15.58 58,13 53.54,8.54 JP2.4
P28
  Top 0.203: IC4.28 59,15.71 59,11.5 56.08,8.58 JP2.3
RTCK1
  Top 0.203: IC4.33 57.9,22.47 R7.1
SK  (via drill 0.51)
  Top 0.203: IC1.62 27.65,35.21 v28.11,35.68 28.5,36.06 IC2.2
  Top 0.254: RN3.3 29.24,40.36 28.5,39.61 IC2.2
  Bottom 0.203: v28.11,35.68 25.83,37.96 22.5,37.96 JP3.4
TCK1
  Top 0.203: RN1.4 58.57,28.03 57.83,27.29 57.83,26.46 IC4.34
TDI1
  Top 0.203: RN1.2 57.7,29.73 IC4.37
TDO1
  Top 0.203: IC4.32 58.52,20.71 RN2.1
TMS1
  Top 0.203: RN1.3 58.03,28.93 IC4.36
TRST1
  Top 0.203: RN1.1 57.46,30.62 IC4.38
TSRST1
  Top 0.203: IC4.31 58.29,19.82 RN2.2
V_TARGET  (via drill 0.51)
  Top 0.305: IC4.26 55.38,17.06 C20.2 | R12.2 21.82,3.65 v22.86,4.69
  Top 0.406: R8.1 58.48,38.8 D1.C 58.48,33.94 58.29,33.75 | v52.24,20.94 52.24,20.2 IC4.26 | 58.29,33.75 C22.+ | v56.25,33.75 58.29,33.75
  Bottom 0.406: v56.25,33.75 56.32,33.68 56.32,27.31 52.24,23.23 v52.24,20.94 40.3,9 27.17,9 v22.86,4.69
V_TARGET_UNREG
  Top 0.406: JTAG.2 JTAG.1 72.23,37.24 70.96,38.51 R8.2 | R8.2 61.38,38.66 | R8.2 61.27,38.77 | R8.2 61.53,44.74 JP4.2
VPHY
  Top 0.254: IC1.4 22.25,26.75 21.5,27.5 17.81,27.5 C13.2
  Top 0.406: L2.1 13.9,27.27 15.54,27.27 C11.+ 17.72,27.51 C13.2
VPLL
  Top 0.254: IC1.9 20.75,24.25 20.24,23.74 C14.2 20.13,22.38 C12.+ 16.29,22.38 L1.1

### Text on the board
tNames: Self powered | (1.5-3.3v max) | Target power: | Bus Blaster | CS | SK | DAT | 3V3 | GND | 3V3 | GND | TDO | TDI | TCK | TMS | (3.3V 200mA max) | MAX 3.3V | VTG | VTG | TRST | TDI | TMS | TCK | JER | RTCK | GND | v.trocio | IAN LESNET | TDO | TSRST | DBGRQ | Bus Blaster | DBGACK | v3b | FEB 2012 | P19 | P20 | P21 | P22 | P23 | P27 | P28 | GND | 3V3
bNames: Target power: | 3V3 | GND | TDO | TDI | TCK | TMS | Self powered | CS | SK | (1.5-3.3v max) | 3V3 | GND | Bus Blaster | DATA | (3.3V 200mA max) | VTG | VTG | TRST | TDI | TMS | TCK | RTCK | GND | TDO | TSRST | Bus Blaster v3b | DBGRQ | DBGACK | http://dangerousprototypes.com | P19 | P20 | P21 | P22 | P23 | P27 | P28 | GND | 3V3 | Fulfillment by: | Seeed Studio | seeedstudio.com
